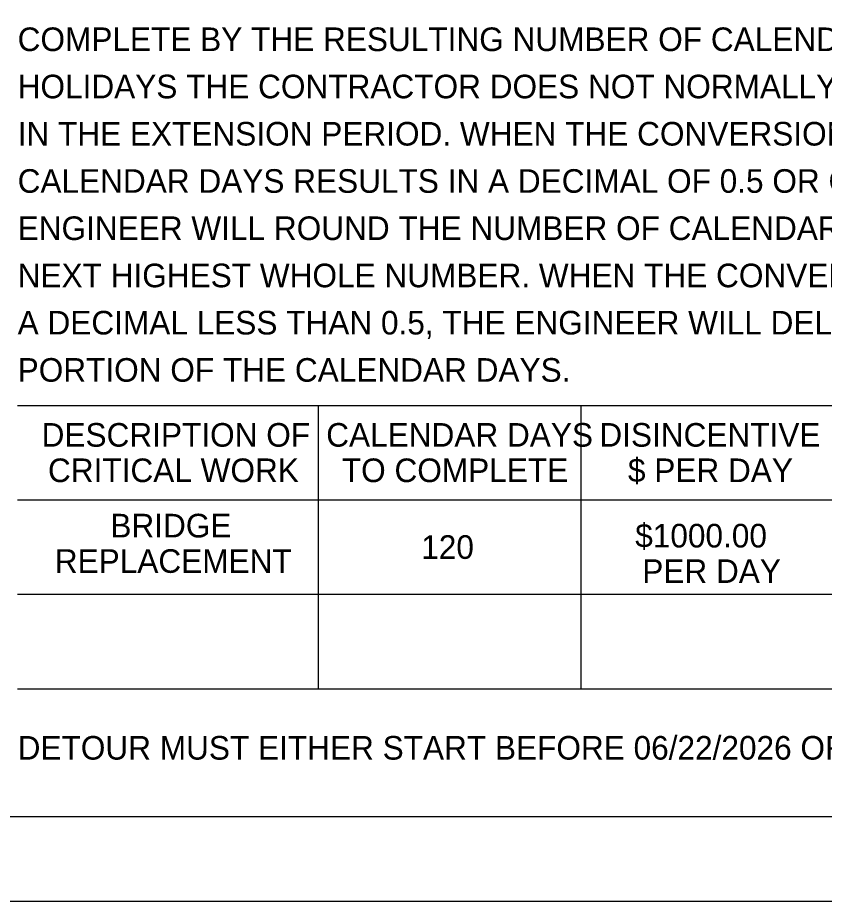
# Model space of a CAD drawing. Extents: x -1.3 to 43.7, y -2.4 to 22.
# Drawn here: x 24.66 to 29.44, y 0 to 5.24 of the extents above; entities that cross this region are included whole.
import ezdxf

# ---------------------------------------------------------------- set-up
doc = ezdxf.new("R2010")
doc.units = 0
for name, color, linetype in [('SH_Border', 7, 'Continuous'), ('SH_Cut_Line', 7, 'Continuous'), ('SH_Text', 7, 'Continuous')]:
    doc.layers.add(name, color=color, linetype=linetype)

msp = doc.modelspace()

# ---------------------------------------------------------------- linework, layer by layer
at = {"layer": 'SH_Border'}
msp.add_lwpolyline([(1.5, 21.5), (33.5, 21.5), (33.5, 0.5), (1.5, 0.5)], close=True, dxfattribs=at)
at = {"layer": 'SH_Cut_Line'}
msp.add_lwpolyline([(0, 0), (34, 0), (34, 22), (0, 22)], close=True, dxfattribs=at)
at = {"layer": 'SH_Text'}
for p, q in [((24.66, 2.94), (31.1, 2.94)), ((26.4412, 2.94), (26.4412, 1.26)), ((27.9977, 2.94), (27.9977, 1.26)), ((24.66, 2.38), (31.1, 2.38)), ((24.66, 1.82), (31.1, 1.82)), ((24.66, 1.26), (31.1, 1.26))]:
    msp.add_line(p, q, dxfattribs=at)

# ---------------------------------------------------------------- texts
for s, p in [('COMPLETE BY THE RESULTING NUMBER OF CALENDAR DAYS PLUS ANY ', (24.66, 5.04)), ('HOLIDAYS THE CONTRACTOR DOES NOT NORMALLY WORK THAT OCCUR ', (24.66, 4.76)), ('IN THE EXTENSION PERIOD. WHEN THE CONVERSION OF WORKDAYS TO ', (24.66, 4.48)), ('CALENDAR DAYS RESULTS IN A DECIMAL OF 0.5 OR GREATER, THE ', (24.66, 4.2)), ('ENGINEER WILL ROUND THE NUMBER OF CALENDAR DAYS TO THE ', (24.66, 3.92)), ('NEXT HIGHEST WHOLE NUMBER. WHEN THE CONVERSION RESULTS IN ', (24.66, 3.64)), ('A DECIMAL LESS THAN 0.5, THE ENGINEER WILL DELETE THE DECIMAL ', (24.66, 3.36)), ('PORTION OF THE CALENDAR DAYS.', (24.66, 3.08)), ('DESCRIPTION OF', (24.8021, 2.695)), ('CALENDAR DAYS ', (26.489, 2.695)), ('DISINCENTIVE ', (28.108, 2.695)), ('CRITICAL WORK', (24.8398, 2.485)), ('TO COMPLETE', (26.5816, 2.485)), ('$ PER DAY', (28.2774, 2.485)), ('BRIDGE', (25.2096, 2.1571)), ('$1000.00', (28.3205, 2.0975)), ('120', (27.0521, 2.03)), ('REPLACEMENT', (24.8802, 1.9471)), ('PER DAY', (28.3623, 1.8875)), ('DETOUR MUST EITHER START BEFORE 06/22/2026 OR AFTER 07/05/2026.', (24.66, 0.84))]:
    msp.add_text(s, height=0.14, dxfattribs=at).set_placement(p)

doc.saveas('drawing.dxf')
